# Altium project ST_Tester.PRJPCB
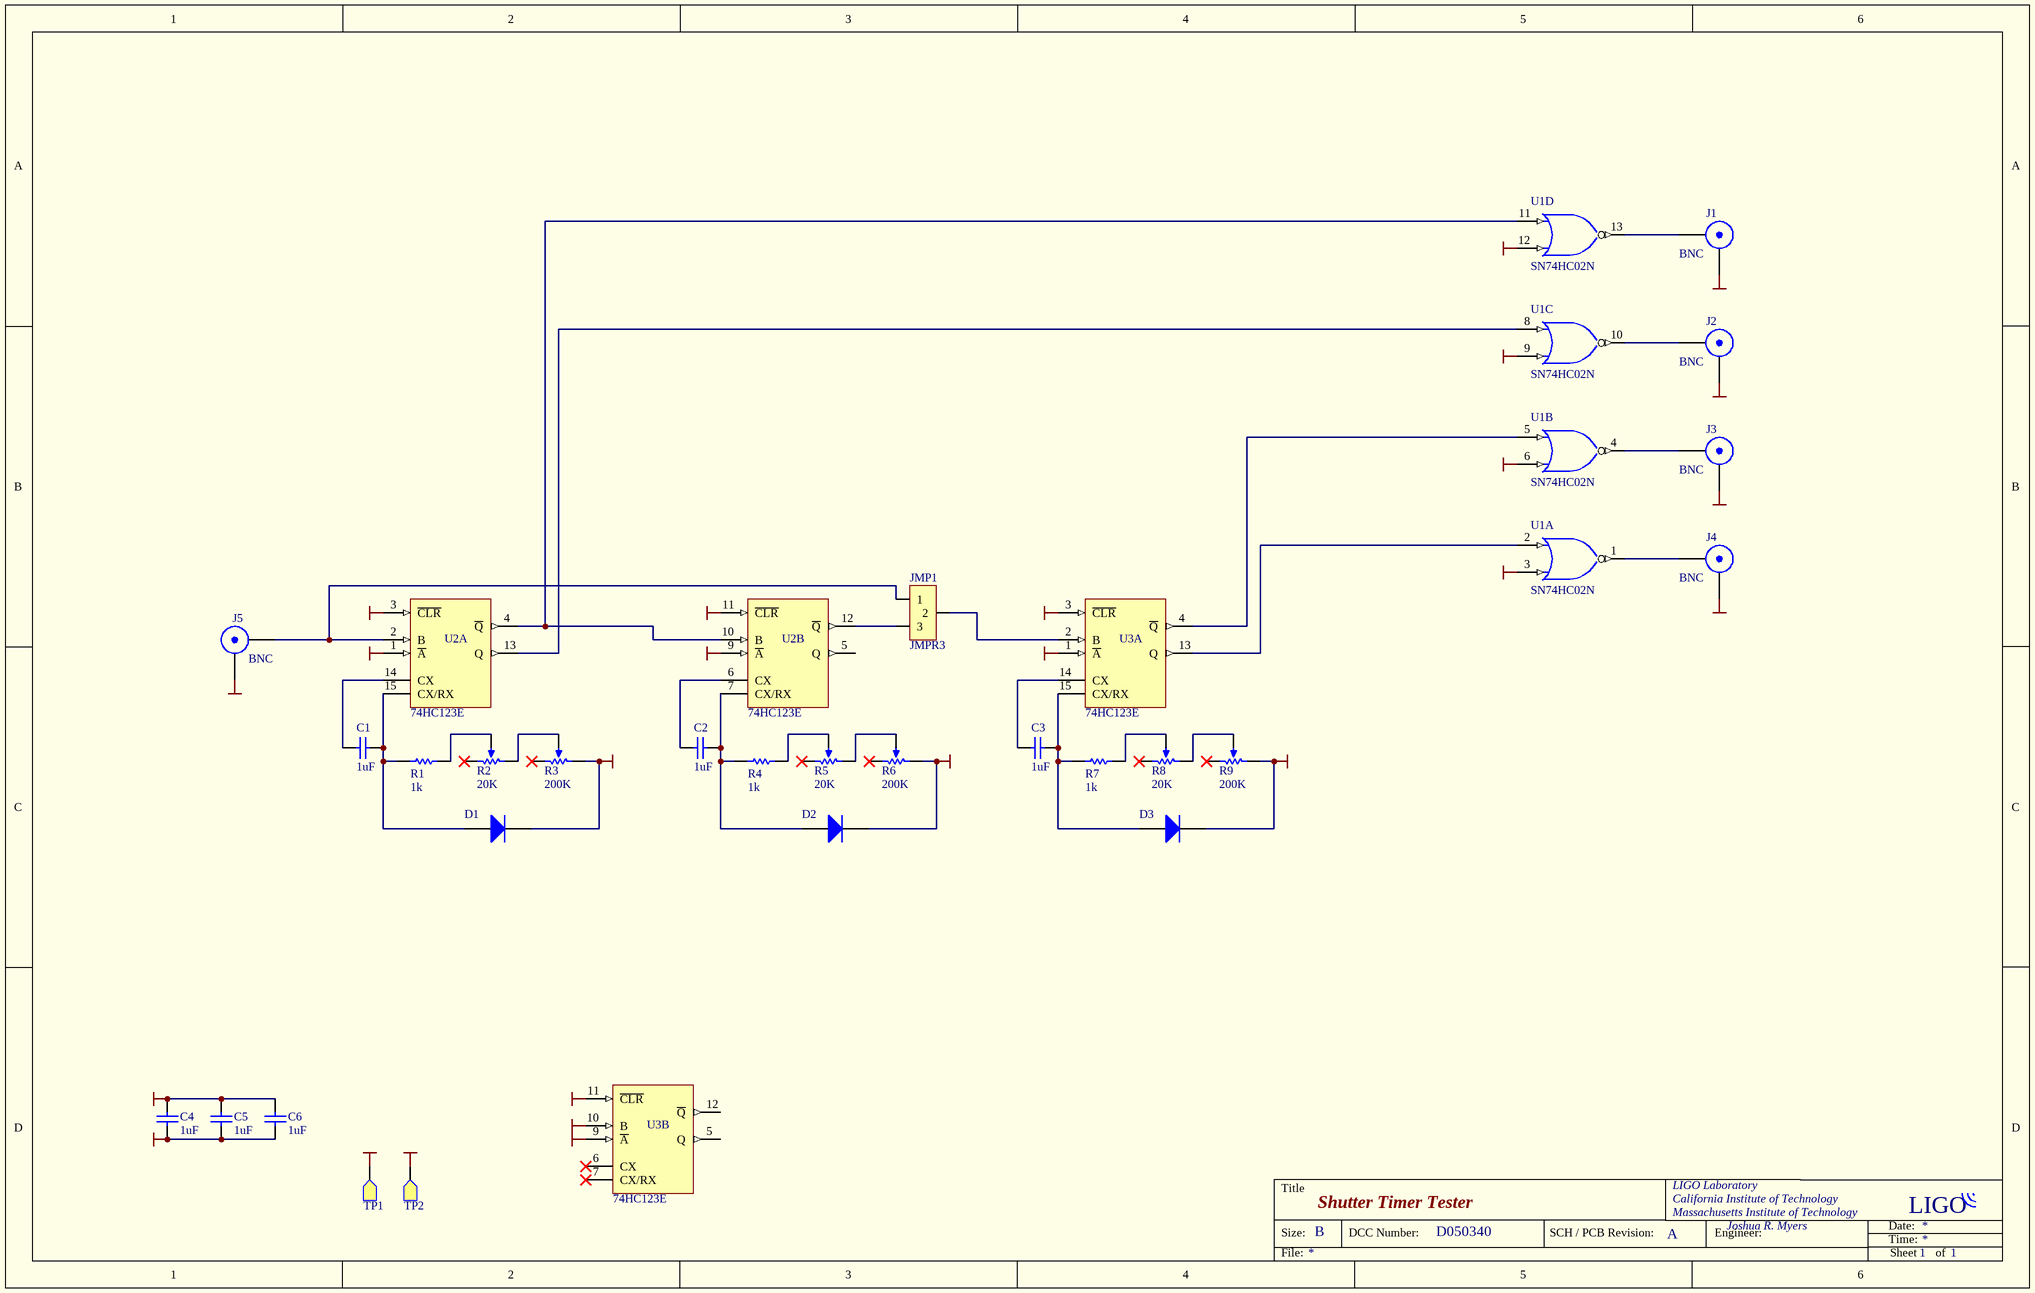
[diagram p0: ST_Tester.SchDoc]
1 sheet, 29 parts. Net scope: global (net labels, ports and power ports of the same name join across sheets).
Board file: ST_Tester.PcbDoc

## Sheet ST_Tester.SchDoc: Shutter Timer Tester
size B; PageSetup: Record=PageOptions|CenterHorizontal=True|CenterVertical=True|PrintScale=1.12|XCorrection=1.00|YCorrection=1.00|PrintKind=2|BorderSize=5000000|LeftOffset=0|BottomOffset=0|Orientation=2|PaperLength=1000|PaperWidth=1000|Scale=100|PaperSource=7|PrintQuality=-4|MediaType=1|DitherType=10|PaperKind=11 x 17|PrintScaleMode=1; Organization: LIGO Laboratory; Address1: California Institute of Technology; Address2: Massachusetts Institute of Technology; Address3: Joshua R. Myers; DocumentNumber: D050340; Revision: A; SheetNumber: 1; SheetTotal: 1

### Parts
C1  1uF  [CR3216-1206]
C2  1uF  [CR3216-1206]
C3  1uF  [CR3216-1206]
C4  1uF  [CR3216-1206]
C5  1uF  [CR3216-1206]
C6  1uF  [CR3216-1206]
D1  Diode 1N4148  [DIO7.1-3.9x1.9]  (value not drawn)
D2  Diode 1N4148  [DIO7.1-3.9x1.9]  (value not drawn)
D3  Diode 1N4148  [DIO7.1-3.9x1.9]  (value not drawn)
J1  BNC  [BNC1]
J2  BNC  [BNC1]
J3  BNC  [BNC1]
J4  BNC  [BNC1]
J5  BNC  [BNC1]
JMP1  JMPR3  [hdr1x3]
R1  1k  [CR3216-1206]
R2  value 20K  [Pot, Vert]  (hidden comment: RPot)
R3  value 200K  [Pot, Vert]  (hidden comment: RPot)
R4  1k  [CR3216-1206]
R5  value 20K  [Pot, Vert]  (hidden comment: RPot)
R6  value 200K  [Pot, Vert]  (hidden comment: RPot)
R7  1k  [CR3216-1206]
R8  value 20K  [Pot, Vert]  (hidden comment: RPot)
R9  value 200K  [Pot, Vert]  (hidden comment: RPot)
TP1  TP  [TP1]  (value not drawn)
TP2  TP  [TP1]  (value not drawn)
U1  SN74HC02N  [N014]  (parts A,B,C,D of 4)
U2  74HC123E  [DIP-16]  (parts A,B of 2)
U3  74HC123E  [DIP-16]  (parts A,B of 2)

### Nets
GND: C4.1 C5.1 C6.1 J1.2(Y) J2.2(Y) J3.2(Y) J4.2(Y) J5.2(Y) TP2.1 U1.3(B) U1.6(B) U1.7(GND) U1.9(B) U1.12(B) U2.1(~{A}) U2.8(GND) U2.9(~{A}) U3.1(~{A}) U3.8(GND) U3.9(~{A})
VCC: C4.2 C5.2 C6.2 D1.2(K) D2.2(K) D3.2(K) R3.2(BOT) R6.2(BOT) R9.2(BOT) TP1.1 U1.14(VCC) U2.3(~{CLR}) U2.11(~{CLR}) U2.16(VCC) U3.3(~{CLR}) U3.10(B) U3.11(~{CLR}) U3.16(VCC)
NetC1_1: C1.1 U2.14(CX)
NetC1_2: C1.2 D1.1(A) R1.1 U2.15(CX/RX)
NetC2_1: C2.1 U2.6(CX)
NetC2_2: C2.2 D2.1(A) R4.1 U2.7(CX/RX)
NetC3_1: C3.1 U3.14(CX)
NetC3_2: C3.2 D3.1(A) R7.1 U3.15(CX/RX)
NetJ1_1: J1.1(X) U1.13(Y)
NetJ2_1: J2.1(X) U1.10(Y)
NetJ3_1: J3.1(X) U1.4(Y)
NetJ4_1: J4.1(X) U1.1(Y)
NetJ5_1: J5.1(X) JMP1.1 U2.2(B)
NetJMP1_2: JMP1.2 U3.2(B)
NetJMP1_3: JMP1.3 U2.12(~{Q})
NetR1_2: R1.2 R2.3(TAP)
NetR2_2: R2.2(BOT) R3.3(TAP)
NetR4_2: R4.2 R5.3(TAP)
NetR5_2: R5.2(BOT) R6.3(TAP)
NetR7_2: R7.2 R8.3(TAP)
NetR8_2: R8.2(BOT) R9.3(TAP)
NetU1_2: U1.2(A) U3.13(Q)
NetU1_5: U1.5(A) U3.4(~{Q})
NetU1_8: U1.8(A) U2.13(Q)
NetU1_11: U1.11(A) U2.4(~{Q}) U2.10(B)

Not connected (* = marked no-connect by the designer): R2 1(TOP)*; R3 1(TOP)*; R5 1(TOP)*; R6 1(TOP)*; R8 1(TOP)*; R9 1(TOP)*; U2 5(Q); U3 5(Q) 6(CX)* 7(CX/RX)* 12(~{Q})

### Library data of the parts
C1-C6 = Cap Semi: Capacitor (Semiconductor SIM Model); Part Number: PCC1893CT-ND
D1-D3 = Diode 1N4148: High Conductance Fast Diode; Part Number: 1N4148DICT-ND; Revision 1: 11-Jul-2000: SIM Model Added.; Revision 2: 17-Jul-2002: Re-released for DXP Platform.; Code - JEDEC: DO-204-AH
J1-J5 = BNC: BNC Elbow Connector; Part Number: A24494-ND
JMP1 = JMPR3: Part Number: WM6503-ND
R1 R4 R7 = Res1: Resistor; Part Number: P1.00KFCT-ND
R2 R5 R8 = RPot: Potentiometer; Part Number: 3296Y-203-ND; Set Position: 0.5
R3 R6 R9 = RPot: Potentiometer; Part Number: 3296Y-204-ND; Set Position: 0.5
TP1 = TP: Part Number: 5005K-ND
TP2 = TP: Part Number: 5006K-ND
U1 = SN74HC02N: Quadruple 2-Input Positive-NOR Gate; Part Number: 296-1564-5-ND; Package Information: Latest Revision: Oct-1995
U2 U3 = SN74LS123D: Retriggerable Monostable Multivibrator; Part Number: 296-9171-5-ND; Package Information: Latest Revision: Jan-1998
